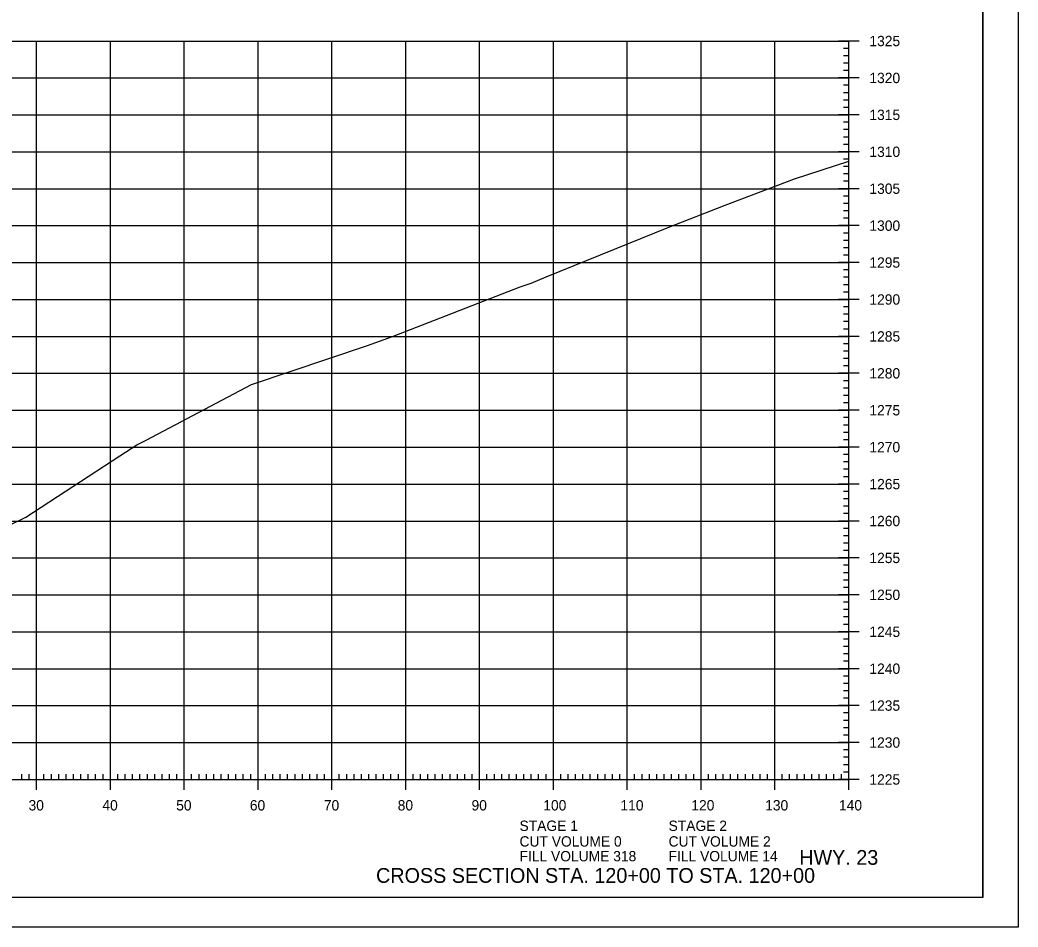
# Model space of a CAD drawing. Extents: x 1406028 to 1412453, y 321733 to 325986.
# Drawn here: x 1406617.6 to 1406752.8, y 325559.4 to 325682.3 of the extents above; entities that cross this region are included whole.
import ezdxf

# ---------------------------------------------------------------- set-up
doc = ezdxf.new("R2010")
doc.units = 0
for name, color, linetype in [('R_Axis', 7, 'Continuous'), ('R_Axis Annot', 7, 'Continuous'), ('R_Border', 7, 'Continuous'), ('R_Draft', 7, 'Continuous'), ('R_Exist Surface', 7, 'Continuous'), ('R_Grid', 7, 'Continuous'), ('R_No Plot', 7, 'Continuous')]:
    doc.layers.add(name, color=color, linetype=linetype)

msp = doc.modelspace()

# ---------------------------------------------------------------- linework, layer by layer
at = {"layer": 'R_Axis'}
for p, q in [((1406731.29, 325679.4), (1406728.49, 325679.4)), ((1406729.89, 325579.4), (1406729.89, 325679.4)), ((1406729.89, 325678.4), (1406729.19, 325678.4)), ((1406729.89, 325677.4), (1406729.19, 325677.4)), ((1406729.89, 325676.4), (1406729.19, 325676.4)), ((1406729.89, 325675.4), (1406729.19, 325675.4)), ((1406731.29, 325674.4), (1406728.49, 325674.4)), ((1406729.89, 325673.4), (1406729.19, 325673.4)), ((1406729.89, 325672.4), (1406729.19, 325672.4)), ((1406729.89, 325671.4), (1406729.19, 325671.4)), ((1406729.89, 325670.4), (1406729.19, 325670.4)), ((1406731.29, 325669.4), (1406728.49, 325669.4)), ((1406729.89, 325668.4), (1406729.19, 325668.4)), ((1406729.89, 325667.4), (1406729.19, 325667.4)), ((1406729.89, 325666.4), (1406729.19, 325666.4)), ((1406729.89, 325665.4), (1406729.19, 325665.4)), ((1406731.29, 325664.4), (1406728.49, 325664.4)), ((1406729.89, 325663.4), (1406729.19, 325663.4)), ((1406729.89, 325662.4), (1406729.19, 325662.4)), ((1406729.89, 325661.4), (1406729.19, 325661.4)), ((1406731.29, 325659.4), (1406728.49, 325659.4)), ((1406729.89, 325660.4), (1406729.19, 325660.4)), ((1406729.89, 325658.4), (1406729.19, 325658.4)), ((1406729.89, 325657.4), (1406729.19, 325657.4)), ((1406729.89, 325656.4), (1406729.19, 325656.4)), ((1406729.89, 325655.4), (1406729.19, 325655.4)), ((1406731.29, 325654.4), (1406728.49, 325654.4)), ((1406729.89, 325653.4), (1406729.19, 325653.4)), ((1406729.89, 325652.4), (1406729.19, 325652.4)), ((1406729.89, 325651.4), (1406729.19, 325651.4)), ((1406729.89, 325650.4), (1406729.19, 325650.4)), ((1406731.29, 325649.4), (1406728.49, 325649.4)), ((1406729.89, 325648.4), (1406729.19, 325648.4)), ((1406729.89, 325647.4), (1406729.19, 325647.4)), ((1406729.89, 325646.4), (1406729.19, 325646.4)), ((1406731.29, 325644.4), (1406728.49, 325644.4)), ((1406729.89, 325645.4), (1406729.19, 325645.4)), ((1406729.89, 325643.4), (1406729.19, 325643.4)), ((1406729.89, 325642.4), (1406729.19, 325642.4)), ((1406729.89, 325641.4), (1406729.19, 325641.4)), ((1406729.89, 325640.4), (1406729.19, 325640.4)), ((1406731.29, 325639.4), (1406728.49, 325639.4)), ((1406729.89, 325638.4), (1406729.19, 325638.4)), ((1406729.89, 325637.4), (1406729.19, 325637.4)), ((1406729.89, 325636.4), (1406729.19, 325636.4)), ((1406729.89, 325635.4), (1406729.19, 325635.4)), ((1406731.29, 325634.4), (1406728.49, 325634.4)), ((1406729.89, 325633.4), (1406729.19, 325633.4)), ((1406729.89, 325632.4), (1406729.19, 325632.4)), ((1406729.89, 325631.4), (1406729.19, 325631.4)), ((1406731.29, 325629.4), (1406728.49, 325629.4)), ((1406729.89, 325630.4), (1406729.19, 325630.4)), ((1406729.89, 325628.4), (1406729.19, 325628.4)), ((1406729.89, 325627.4), (1406729.19, 325627.4)), ((1406729.89, 325626.4), (1406729.19, 325626.4)), ((1406729.89, 325625.4), (1406729.19, 325625.4)), ((1406731.29, 325624.4), (1406728.49, 325624.4)), ((1406729.89, 325623.4), (1406729.19, 325623.4)), ((1406729.89, 325622.4), (1406729.19, 325622.4)), ((1406729.89, 325621.4), (1406729.19, 325621.4)), ((1406729.89, 325620.4), (1406729.19, 325620.4)), ((1406731.29, 325619.4), (1406728.49, 325619.4)), ((1406729.89, 325618.4), (1406729.19, 325618.4)), ((1406729.89, 325617.4), (1406729.19, 325617.4)), ((1406729.89, 325616.4), (1406729.19, 325616.4)), ((1406729.89, 325615.4), (1406729.19, 325615.4)), ((1406731.29, 325614.4), (1406728.49, 325614.4)), ((1406729.89, 325613.4), (1406729.19, 325613.4)), ((1406729.89, 325612.4), (1406729.19, 325612.4)), ((1406729.89, 325611.4), (1406729.19, 325611.4)), ((1406731.29, 325609.4), (1406728.49, 325609.4)), ((1406729.89, 325610.4), (1406729.19, 325610.4)), ((1406729.89, 325608.4), (1406729.19, 325608.4)), ((1406729.89, 325607.4), (1406729.19, 325607.4)), ((1406729.89, 325606.4), (1406729.19, 325606.4)), ((1406729.89, 325605.4), (1406729.19, 325605.4)), ((1406731.29, 325604.4), (1406728.49, 325604.4)), ((1406729.89, 325603.4), (1406729.19, 325603.4)), ((1406729.89, 325602.4), (1406729.19, 325602.4)), ((1406729.89, 325601.4), (1406729.19, 325601.4)), ((1406729.89, 325600.4), (1406729.19, 325600.4)), ((1406731.29, 325599.4), (1406728.49, 325599.4)), ((1406729.89, 325598.4), (1406729.19, 325598.4)), ((1406729.89, 325597.4), (1406729.19, 325597.4)), ((1406729.89, 325596.4), (1406729.19, 325596.4)), ((1406731.29, 325594.4), (1406728.49, 325594.4)), ((1406729.89, 325595.4), (1406729.19, 325595.4)), ((1406729.89, 325593.4), (1406729.19, 325593.4)), ((1406729.89, 325592.4), (1406729.19, 325592.4)), ((1406729.89, 325591.4), (1406729.19, 325591.4)), ((1406729.89, 325590.4), (1406729.19, 325590.4)), ((1406731.29, 325589.4), (1406728.49, 325589.4)), ((1406729.89, 325588.4), (1406729.19, 325588.4)), ((1406729.89, 325587.4), (1406729.19, 325587.4)), ((1406729.89, 325586.4), (1406729.19, 325586.4)), ((1406729.89, 325585.4), (1406729.19, 325585.4)), ((1406731.29, 325584.4), (1406728.49, 325584.4)), ((1406729.89, 325583.4), (1406729.19, 325583.4)), ((1406729.89, 325582.4), (1406729.19, 325582.4)), ((1406619.89, 325578), (1406619.89, 325580.8)), ((1406629.89, 325578), (1406629.89, 325580.8)), ((1406639.89, 325578), (1406639.89, 325580.8)), ((1406649.89, 325578), (1406649.89, 325580.8)), ((1406659.89, 325578), (1406659.89, 325580.8)), ((1406669.89, 325578), (1406669.89, 325580.8)), ((1406679.89, 325578), (1406679.89, 325580.8)), ((1406689.89, 325578), (1406689.89, 325580.8)), ((1406699.89, 325578), (1406699.89, 325580.8)), ((1406709.89, 325578), (1406709.89, 325580.8)), ((1406719.89, 325578), (1406719.89, 325580.8)), ((1406729.89, 325581.4), (1406729.19, 325581.4)), ((1406729.89, 325578), (1406729.89, 325580.8)), ((1406449.89, 325579.4), (1406729.89, 325579.4)), ((1406617.89, 325579.4), (1406617.89, 325580.1)), ((1406618.89, 325579.4), (1406618.89, 325580.1)), ((1406620.89, 325579.4), (1406620.89, 325580.1)), ((1406621.89, 325579.4), (1406621.89, 325580.1)), ((1406622.89, 325579.4), (1406622.89, 325580.1)), ((1406623.89, 325579.4), (1406623.89, 325580.1)), ((1406624.89, 325579.4), (1406624.89, 325580.1)), ((1406625.89, 325579.4), (1406625.89, 325580.1)), ((1406626.89, 325579.4), (1406626.89, 325580.1)), ((1406627.89, 325579.4), (1406627.89, 325580.1)), ((1406628.89, 325579.4), (1406628.89, 325580.1)), ((1406630.89, 325579.4), (1406630.89, 325580.1)), ((1406631.89, 325579.4), (1406631.89, 325580.1)), ((1406632.89, 325579.4), (1406632.89, 325580.1)), ((1406633.89, 325579.4), (1406633.89, 325580.1)), ((1406634.89, 325579.4), (1406634.89, 325580.1)), ((1406635.89, 325579.4), (1406635.89, 325580.1)), ((1406636.89, 325579.4), (1406636.89, 325580.1)), ((1406637.89, 325579.4), (1406637.89, 325580.1)), ((1406638.89, 325579.4), (1406638.89, 325580.1)), ((1406640.89, 325579.4), (1406640.89, 325580.1)), ((1406641.89, 325579.4), (1406641.89, 325580.1)), ((1406642.89, 325579.4), (1406642.89, 325580.1)), ((1406643.89, 325579.4), (1406643.89, 325580.1)), ((1406644.89, 325579.4), (1406644.89, 325580.1)), ((1406645.89, 325579.4), (1406645.89, 325580.1)), ((1406646.89, 325579.4), (1406646.89, 325580.1)), ((1406647.89, 325579.4), (1406647.89, 325580.1)), ((1406648.89, 325579.4), (1406648.89, 325580.1)), ((1406650.89, 325579.4), (1406650.89, 325580.1)), ((1406651.89, 325579.4), (1406651.89, 325580.1)), ((1406652.89, 325579.4), (1406652.89, 325580.1)), ((1406653.89, 325579.4), (1406653.89, 325580.1)), ((1406654.89, 325579.4), (1406654.89, 325580.1)), ((1406655.89, 325579.4), (1406655.89, 325580.1)), ((1406656.89, 325579.4), (1406656.89, 325580.1)), ((1406657.89, 325579.4), (1406657.89, 325580.1)), ((1406658.89, 325579.4), (1406658.89, 325580.1)), ((1406660.89, 325579.4), (1406660.89, 325580.1)), ((1406661.89, 325579.4), (1406661.89, 325580.1)), ((1406662.89, 325579.4), (1406662.89, 325580.1)), ((1406663.89, 325579.4), (1406663.89, 325580.1)), ((1406664.89, 325579.4), (1406664.89, 325580.1)), ((1406665.89, 325579.4), (1406665.89, 325580.1)), ((1406666.89, 325579.4), (1406666.89, 325580.1)), ((1406667.89, 325579.4), (1406667.89, 325580.1)), ((1406668.89, 325579.4), (1406668.89, 325580.1)), ((1406670.89, 325579.4), (1406670.89, 325580.1)), ((1406671.89, 325579.4), (1406671.89, 325580.1)), ((1406672.89, 325579.4), (1406672.89, 325580.1)), ((1406673.89, 325579.4), (1406673.89, 325580.1)), ((1406674.89, 325579.4), (1406674.89, 325580.1)), ((1406675.89, 325579.4), (1406675.89, 325580.1)), ((1406676.89, 325579.4), (1406676.89, 325580.1)), ((1406677.89, 325579.4), (1406677.89, 325580.1)), ((1406678.89, 325579.4), (1406678.89, 325580.1)), ((1406680.89, 325579.4), (1406680.89, 325580.1)), ((1406681.89, 325579.4), (1406681.89, 325580.1)), ((1406682.89, 325579.4), (1406682.89, 325580.1)), ((1406683.89, 325579.4), (1406683.89, 325580.1)), ((1406684.89, 325579.4), (1406684.89, 325580.1)), ((1406685.89, 325579.4), (1406685.89, 325580.1)), ((1406686.89, 325579.4), (1406686.89, 325580.1)), ((1406687.89, 325579.4), (1406687.89, 325580.1)), ((1406688.89, 325579.4), (1406688.89, 325580.1)), ((1406690.89, 325579.4), (1406690.89, 325580.1)), ((1406691.89, 325579.4), (1406691.89, 325580.1)), ((1406692.89, 325579.4), (1406692.89, 325580.1)), ((1406693.89, 325579.4), (1406693.89, 325580.1)), ((1406694.89, 325579.4), (1406694.89, 325580.1)), ((1406695.89, 325579.4), (1406695.89, 325580.1)), ((1406696.89, 325579.4), (1406696.89, 325580.1)), ((1406697.89, 325579.4), (1406697.89, 325580.1)), ((1406698.89, 325579.4), (1406698.89, 325580.1)), ((1406700.89, 325579.4), (1406700.89, 325580.1)), ((1406701.89, 325579.4), (1406701.89, 325580.1)), ((1406702.89, 325579.4), (1406702.89, 325580.1)), ((1406703.89, 325579.4), (1406703.89, 325580.1)), ((1406704.89, 325579.4), (1406704.89, 325580.1)), ((1406705.89, 325579.4), (1406705.89, 325580.1)), ((1406706.89, 325579.4), (1406706.89, 325580.1)), ((1406707.89, 325579.4), (1406707.89, 325580.1)), ((1406708.89, 325579.4), (1406708.89, 325580.1)), ((1406710.89, 325579.4), (1406710.89, 325580.1)), ((1406711.89, 325579.4), (1406711.89, 325580.1)), ((1406712.89, 325579.4), (1406712.89, 325580.1)), ((1406713.89, 325579.4), (1406713.89, 325580.1)), ((1406714.89, 325579.4), (1406714.89, 325580.1)), ((1406715.89, 325579.4), (1406715.89, 325580.1)), ((1406716.89, 325579.4), (1406716.89, 325580.1)), ((1406717.89, 325579.4), (1406717.89, 325580.1)), ((1406718.89, 325579.4), (1406718.89, 325580.1)), ((1406720.89, 325579.4), (1406720.89, 325580.1)), ((1406721.89, 325579.4), (1406721.89, 325580.1)), ((1406722.89, 325579.4), (1406722.89, 325580.1)), ((1406723.89, 325579.4), (1406723.89, 325580.1)), ((1406724.89, 325579.4), (1406724.89, 325580.1)), ((1406725.89, 325579.4), (1406725.89, 325580.1)), ((1406726.89, 325579.4), (1406726.89, 325580.1)), ((1406727.89, 325579.4), (1406727.89, 325580.1)), ((1406731.29, 325579.4), (1406728.49, 325579.4)), ((1406728.89, 325579.4), (1406728.89, 325580.1)), ((1406729.89, 325580.4), (1406729.19, 325580.4))]:
    msp.add_line(p, q, dxfattribs=at)
at = {"layer": 'R_Border'}
for q in [(1406748.07, 325768.86), (1406431.89, 325563.4)]:
    msp.add_line((1406748.07, 325563.4), q, dxfattribs=at)
at = {"layer": 'R_Exist Surface'}
msp.add_lwpolyline([(1406616.2, 325613.82), (1406618.45, 325614.9), (1406631.18, 325623.22), (1406633.48, 325624.7), (1406634.73, 325625.36), (1406649.02, 325632.89), (1406664.69, 325638.15), (1406668.09, 325639.37), (1406685.4, 325646.09), (1406686.88, 325646.63), (1406688.89, 325647.46), (1406705.54, 325654.17), (1406713.17, 325657.16), (1406722.54, 325660.72), (1406729.89, 325663.14)], dxfattribs=at)
at = {"layer": 'R_Grid'}
for p, q in [((1406449.89, 325679.4), (1406729.89, 325679.4)), ((1406619.89, 325579.4), (1406619.89, 325679.4)), ((1406629.89, 325579.4), (1406629.89, 325679.4)), ((1406639.89, 325579.4), (1406639.89, 325679.4)), ((1406649.89, 325579.4), (1406649.89, 325679.4)), ((1406659.89, 325579.4), (1406659.89, 325679.4)), ((1406669.89, 325579.4), (1406669.89, 325679.4)), ((1406679.89, 325579.4), (1406679.89, 325679.4)), ((1406689.89, 325579.4), (1406689.89, 325679.4)), ((1406699.89, 325579.4), (1406699.89, 325679.4)), ((1406709.89, 325579.4), (1406709.89, 325679.4)), ((1406719.89, 325579.4), (1406719.89, 325679.4)), ((1406729.89, 325579.4), (1406729.89, 325679.4)), ((1406449.89, 325674.4), (1406729.89, 325674.4)), ((1406449.89, 325669.4), (1406729.89, 325669.4)), ((1406449.89, 325664.4), (1406729.89, 325664.4)), ((1406449.89, 325659.4), (1406729.89, 325659.4)), ((1406449.89, 325654.4), (1406729.89, 325654.4)), ((1406449.89, 325649.4), (1406729.89, 325649.4)), ((1406449.89, 325644.4), (1406729.89, 325644.4)), ((1406449.89, 325639.4), (1406729.89, 325639.4)), ((1406449.89, 325634.4), (1406729.89, 325634.4)), ((1406449.89, 325629.4), (1406729.89, 325629.4)), ((1406449.89, 325624.4), (1406729.89, 325624.4)), ((1406449.89, 325619.4), (1406729.89, 325619.4)), ((1406449.89, 325614.4), (1406729.89, 325614.4)), ((1406449.89, 325609.4), (1406729.89, 325609.4)), ((1406449.89, 325604.4), (1406729.89, 325604.4)), ((1406449.89, 325599.4), (1406729.89, 325599.4)), ((1406449.89, 325594.4), (1406729.89, 325594.4)), ((1406449.89, 325589.4), (1406729.89, 325589.4)), ((1406449.89, 325584.4), (1406729.89, 325584.4)), ((1406449.89, 325579.4), (1406729.89, 325579.4))]:
    msp.add_line(p, q, dxfattribs=at)
at = {"layer": 'R_No Plot'}
msp.add_line((1406419.49, 325559.42), (1406752.82, 325559.42), dxfattribs=at)
for points in [[(1406419.48, 325772.75), (1406752.82, 325772.75), (1406752.82, 325559.41), (1406419.48, 325559.41)], [(1406665.81, 325768.86), (1406685.43, 325768.86), (1406685.43, 325758.98), (1406701.54, 325758.98), (1406724.74, 325758.98), (1406724.74, 325734.64), (1406748.07, 325734.64), (1406748.07, 325563.4), (1406431.89, 325563.4), (1406431.89, 325768.86)]]:
    msp.add_lwpolyline(points, close=True, dxfattribs=at)

# ---------------------------------------------------------------- texts
at = {"layer": 'R_Axis Annot'}
for s, p in [('1325', (1406732.69, 325678.7)), ('1320', (1406732.69, 325673.7)), ('1315', (1406732.69, 325668.7)), ('1310', (1406732.69, 325663.7)), ('1305', (1406732.69, 325658.7)), ('1300', (1406732.69, 325653.7)), ('1295', (1406732.69, 325648.7)), ('1290', (1406732.69, 325643.7)), ('1285', (1406732.69, 325638.7)), ('1280', (1406732.69, 325633.7)), ('1275', (1406732.69, 325628.7)), ('1270', (1406732.69, 325623.7)), ('1265', (1406732.69, 325618.7)), ('1260', (1406732.69, 325613.7)), ('1255', (1406732.69, 325608.7)), ('1250', (1406732.69, 325603.7)), ('1245', (1406732.69, 325598.7)), ('1240', (1406732.69, 325593.7)), ('1235', (1406732.69, 325588.7)), ('1230', (1406732.69, 325583.7)), ('1225', (1406732.69, 325578.7)), ('30', (1406618.8, 325575.2)), ('40', (1406628.8, 325575.2)), ('50', (1406638.8, 325575.2)), ('60', (1406648.77, 325575.2)), ('70', (1406658.8, 325575.2)), ('80', (1406668.8, 325575.2)), ('90', (1406678.8, 325575.2)), ('100', (1406688.52, 325575.2)), ('110', (1406698.97, 325575.2)), ('120', (1406708.57, 325575.2)), ('130', (1406718.57, 325575.2)), ('140', (1406728.57, 325575.2)), ('STAGE 1', (1406685.3, 325572.43)), ('STAGE 2', (1406705.49, 325572.43)), ('CUT VOLUME 0', (1406685.3, 325570.31)), ('CUT VOLUME 2', (1406705.49, 325570.31)), ('FILL VOLUME 318', (1406685.3, 325568.31)), ('FILL VOLUME 14', (1406705.49, 325568.31))]:
    msp.add_text(s, height=1.4, dxfattribs=at).set_placement(p)
at = {"layer": 'R_Draft'}
for s, p in [('HWY. 23', (1406723.19, 325567.84)), ('CROSS SECTION STA. 120+00 TO STA. 120+00', (1406665.87, 325565.4))]:
    msp.add_text(s, height=2, dxfattribs=at).set_placement(p)
at = {"layer": 'R_No Plot'}
for p in [(1406722.5, 325660.67), (1406705.49, 325654.12), (1406686.84, 325646.58), (1406668.05, 325639.32), (1406648.98, 325632.84), (1406633.44, 325624.65), (1406618.41, 325614.85)]:
    msp.add_text('+', height=0.1, dxfattribs=at).set_placement(p)

doc.saveas('drawing.dxf')
